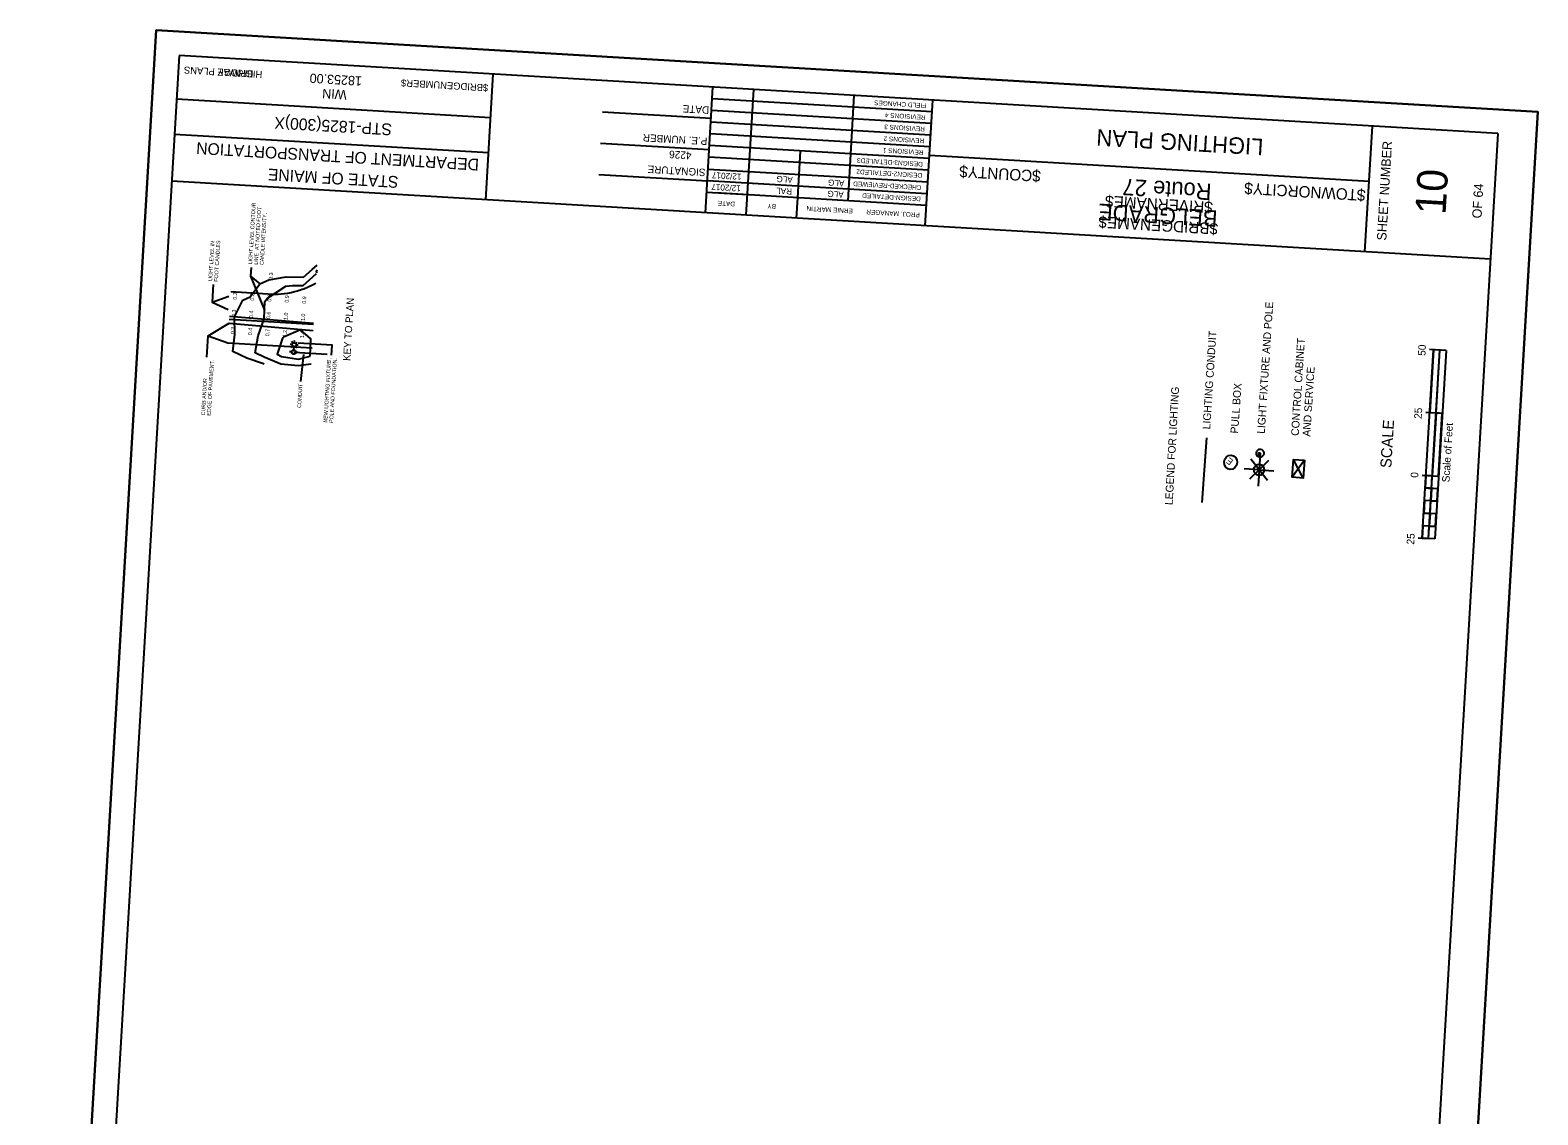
# Model space of a CAD drawing. Extents: x 1111000 to 1111599, y 618328 to 619209.
# Drawn here: x 1111000 to 1111599, y 618778 to 619209 of the extents above; entities that cross this region are included whole.
import ezdxf

# ---------------------------------------------------------------- set-up
doc = ezdxf.new("R2010")
doc.units = 0
for name, color, linetype in [('ANNOTATION', 7, 'Continuous'), ('BORDER', 7, 'Continuous'), ('BRIDGE_TITLE', 7, 'Continuous'), ('D_Lighting', 7, 'Continuous'), ('D_Utilities_Pole_StreetLight', 7, 'Continuous'), ('Default', 7, 'Continuous'), ('H_V CONTROLS', 7, 'Continuous'), ('HIGHWAY_TITLE', 7, 'Continuous'), ('Liting Text', 7, 'Continuous'), ('PLOT BOUNDARY', 7, 'Continuous'), ('Prp Liting', 7, 'Continuous'), ('UTILS GRND', 7, 'Continuous'), ('VSL-LUMINAIRES', 7, 'Continuous')]:
    doc.layers.add(name, color=color, linetype=linetype)

msp = doc.modelspace()

# ---------------------------------------------------------------- linework, layer by layer
at = {"layer": 'ANNOTATION'}
for p, q in [((1111087.16, 619111.54), (1111092.67, 619098.15)), ((1111094.11, 619104.46), (1111079.37, 619105.33)), ((1111071.9, 619101.33), (1111078.55, 619103.6)), ((1111078.62, 619092.89), (1111112.04, 619090.04)), ((1111112.18, 619092.36), (1111078.71, 619094.33)), ((1111112.2, 619092.79), (1111078.78, 619095.64)), ((1111070.35, 619087.89), (1111078.16, 619085.17)), ((1111078.16, 619085.17), (1111111.63, 619083.19)), ((1111102.8, 619081.83), (1111102.8, 619081.88)), ((1111102.96, 619084.58), (1111102.97, 619084.63)), ((1111103.95, 619080.99), (1111103.95, 619080.99)), ((1111103.97, 619081.33), (1111103.97, 619081.33)), ((1111104.3, 619080.97), (1111104.3, 619080.97)), ((1111104.32, 619081.31), (1111104.32, 619081.31)), ((1111105.71, 619084.42), (1111105.71, 619084.46)), ((1111107.09, 619069.78), (1111108.35, 619080.44))]:
    msp.add_line(p, q, dxfattribs=at)
for points in [[(1111092.58, 619076.67), (1111092.38, 619076.72), (1111085.63, 619079.09), (1111080.1, 619081.65), (1111080.93, 619088.5), (1111080.75, 619095.41), (1111084.05, 619102.11), (1111087.08, 619103.34), (1111090.89, 619108.6), (1111094.39, 619110.2), (1111101.35, 619111.33), (1111108.24, 619111.18), (1111111.7, 619114.27), (1111113.59, 619115.96)], [(1111087.37, 619115.05), (1111087.16, 619111.54), (1111090.89, 619108.6)], [(1111111.23, 619076.59), (1111106.12, 619075.95), (1111099.27, 619076.69), (1111092.54, 619079.4), (1111089.05, 619081.12), (1111090.18, 619087.95), (1111092.54, 619094.71), (1111092.81, 619101.59), (1111093.95, 619102.93), (1111101.13, 619107.58), (1111103.85, 619107.84), (1111108.04, 619107.89), (1111113.4, 619112.68)], [(1111072.32, 619108.34), (1111071.9, 619101.33), (1111078.28, 619098.39)], [(1111069.84, 619079.39), (1111070.35, 619087.89), (1111078.62, 619092.89)], [(1111110.84, 619079.84), (1111111.15, 619086.72), (1111106.99, 619090.32), (1111100.25, 619087.36), (1111099.89, 619086.99), (1111097.74, 619080.61), (1111099.46, 619079.75), (1111106.29, 619078.67), (1111110.84, 619079.84)], [(1111119.4, 619080.17), (1111119.64, 619084.23), (1111106.15, 619085.03)]]:
    msp.add_lwpolyline(points, dxfattribs=at)
for centre, major_axis, start_param, end_param in [((1111114.68, 619113.39), (0.86, 1.08), 1.737973, 2.633498), ((1111096.17, 619138.82), (21.5, 26.9), 3.756531, 4.064294), ((1111096.17, 619138.82), (21.5, 26.9), 4.064294, 4.213502), ((1111096.17, 619138.82), (21.5, 26.9), 4.213502, 4.323837), ((1111096.17, 619138.82), (21.5, 26.9), 4.323837, 4.333024)]:
    msp.add_ellipse(centre, major_axis=major_axis, ratio=0.998974, start_param=start_param, end_param=end_param, dxfattribs=at)
at = {"layer": 'BORDER'}
for p, q in [((1111058.79, 619199.23), (1111011.66, 618400.62)), ((1111582.86, 619168.3), (1111058.78, 619199.23)), ((1111180.66, 619141.96), (1111183.6, 619191.86)), ((1111182.57, 619174.51), (1111057.78, 619181.88)), ((1111267.96, 619136.8), (1111270.91, 619186.71)), ((1111270.17, 619174.23), (1111227.01, 619176.78)), ((1111355.31, 619131.64), (1111358.26, 619181.56)), ((1111530.01, 619121.33), (1111532.95, 619171.25)), ((1111181.74, 619160.56), (1111056.96, 619167.93)), ((1111269.43, 619161.76), (1111226.27, 619164.3)), ((1111535.75, 618369.69), (1111582.88, 619168.3)), ((1111531.65, 619149.24), (1111356.96, 619159.55)), ((1111579.92, 619118.39), (1111055.83, 619149.32)), ((1111268.7, 619149.28), (1111225.54, 619151.82))]:
    msp.add_line(p, q, dxfattribs=at)
for points in [[(1111357.97, 619176.91), (1111270.63, 619182.07)], [(1111284.18, 619135.84), (1111287.13, 619185.75)], [(1111324.59, 619141.55), (1111327.06, 619183.4)], [(1111357.69, 619172.26), (1111270.36, 619177.42)], [(1111357.42, 619167.61), (1111270.08, 619172.77)], [(1111357.14, 619162.96), (1111269.81, 619168.11)], [(1111356.59, 619153.66), (1111269.26, 619158.81)], [(1111356.87, 619158.31), (1111269.54, 619163.46)], [(1111304.62, 619142.72), (1111305.72, 619161.32)], [(1111268.99, 619154.16), (1111356.32, 619149.01)], [(1111356.05, 619144.36), (1111268.71, 619149.51)], [(1111284.66, 619143.9), (1111268.44, 619144.86)], [(1111355.77, 619139.71), (1111271.96, 619144.66)], [(1111304.15, 619134.66), (1111304.63, 619142.73)]]:
    msp.add_lwpolyline(points, dxfattribs=at)
at = {"layer": 'D_Lighting'}
for p, q in [((1111487.93, 619034.72), (1111484.62, 619038.92)), ((1111488.35, 619041.3), (1111487.93, 619034.72)), ((1111487.93, 619034.72), (1111491.76, 619038.46)), ((1111506.04, 619038.46), (1111501.03, 619031.77)), ((1111505.48, 619031.42), (1111501.59, 619038.81)), ((1111487.93, 619034.72), (1111482.01, 619035.1)), ((1111487.93, 619034.72), (1111484.1, 619030.98)), ((1111487.93, 619034.72), (1111487.51, 619028.14)), ((1111487.93, 619034.72), (1111493.85, 619034.34)), ((1111487.93, 619034.72), (1111491.24, 619030.52))]:
    msp.add_line(p, q, dxfattribs=at)
msp.add_lwpolyline([(1111506.04, 619038.46), (1111505.48, 619031.42), (1111501.03, 619031.77), (1111501.59, 619038.81)], close=True, dxfattribs=at)
for centre, major_axis in [((1111488.36, 619041.3), (0.11, 1.64)), ((1111487.93, 619034.72), (0.15, 2.24))]:
    msp.add_ellipse(centre, major_axis=major_axis, ratio=0.899857, dxfattribs=at)
at = {"layer": 'D_Utilities_Pole_StreetLight'}
for p, q in [((1111104.59, 619085.19), (1111104.64, 619085.99)), ((1111103.53, 619081.51), (1111102.71, 619081.57)), ((1111103.74, 619084.44), (1111102.94, 619084.49)), ((1111103.94, 619083.86), (1111103.33, 619083.33)), ((1111104.01, 619084.99), (1111103.48, 619085.59)), ((1111104.4, 619082.28), (1111104.49, 619083.59)), ((1111105.07, 619083.79), (1111105.59, 619083.19)), ((1111105.14, 619084.92), (1111105.74, 619085.45)), ((1111105.17, 619081.41), (1111105.99, 619081.36)), ((1111105.34, 619084.34), (1111106.13, 619084.29))]:
    msp.add_line(p, q, dxfattribs=at)
for centre, major_axis in [((1111104.35, 619081.46), (0.512, 0.641)), ((1111104.54, 619084.39), (-0.5, -0.626))]:
    msp.add_ellipse(centre, major_axis=major_axis, ratio=0.998974, dxfattribs=at)
at = {"layer": 'Default'}
msp.add_lwpolyline([(1110999.59, 618360.8), (1111049.67, 619209.32), (1111598.71, 619176.92), (1111548.64, 618328.39)], close=True, dxfattribs=at)
at = {"layer": 'H_V CONTROLS'}
for p, q in [((1111552.76, 619007.51), (1111557.24, 619082.37)), ((1111555.26, 619007.36), (1111559.73, 619082.23)), ((1111562.23, 619082.08), (1111555.68, 619082.47)), ((1111562.23, 619082.08), (1111557.75, 619007.21)), ((1111560.74, 619057.12), (1111554.19, 619057.51)), ((1111552.69, 619032.56), (1111559.25, 619032.17)), ((1111558.95, 619027.18), (1111553.96, 619027.47)), ((1111558.65, 619022.19), (1111553.66, 619022.48)), ((1111558.35, 619017.19), (1111553.36, 619017.49)), ((1111558.05, 619012.2), (1111553.06, 619012.5)), ((1111557.75, 619007.21), (1111551.2, 619007.6))]:
    msp.add_line(p, q, dxfattribs=at)
for points in [[(1111558.24, 619057.27), (1111559.73, 619082.23), (1111557.24, 619082.37), (1111555.75, 619057.42), (1111558.24, 619057.27)], [(1111558.24, 619057.27), (1111556.75, 619032.32), (1111559.25, 619032.17), (1111560.74, 619057.12), (1111558.24, 619057.27)], [(1111556.45, 619027.33), (1111556.75, 619032.32), (1111554.25, 619032.47), (1111553.96, 619027.47), (1111556.45, 619027.33)], [(1111556.15, 619022.33), (1111558.65, 619022.19), (1111558.95, 619027.18), (1111556.45, 619027.33), (1111556.15, 619022.33)], [(1111556.15, 619022.33), (1111553.66, 619022.48), (1111553.36, 619017.49), (1111555.86, 619017.34), (1111556.15, 619022.33)], [(1111555.56, 619012.35), (1111558.05, 619012.2), (1111558.35, 619017.19), (1111555.86, 619017.34), (1111555.56, 619012.35)], [(1111555.56, 619012.35), (1111553.06, 619012.5), (1111552.76, 619007.51), (1111555.26, 619007.36), (1111555.56, 619012.35)]]:
    msp.add_lwpolyline(points, dxfattribs=at)
at = {"layer": 'Liting Text'}
msp.add_line((1111104.35, 619081.46), (1111117.59, 619080.68), dxfattribs=at)
at = {"layer": 'PLOT BOUNDARY'}
msp.add_lwpolyline([(1111548.64, 618328.39), (1111598.71, 619176.92), (1111049.67, 619209.32), (1110999.59, 618360.8)], close=True, dxfattribs=at)
at = {"layer": 'Prp Liting'}
msp.add_line((1111465.3, 619021.72), (1111467.12, 619047.45), dxfattribs=at)
at = {"layer": 'UTILS GRND'}
msp.add_ellipse((1111476.65, 619037.69), major_axis=(-0.18, -2.87), ratio=0.901044, dxfattribs=at)
at = {"layer": 'VSL-LUMINAIRES'}
msp.add_lwpolyline([(1111488.46, 619041.29), (1111487.74, 619041.31), (1111487.73, 619040.55), (1111488.45, 619040.53)], close=True, dxfattribs=at)
msp.add_lwpolyline([(1111488.46, 619041.29), (1111487.74, 619041.31), (1111487.73, 619040.55), (1111488.45, 619040.53)], close=True, dxfattribs=at)
msp.add_lwpolyline([(1111488.35, 619041.3), (1111488.35, 619041.3)], dxfattribs=at)

# ---------------------------------------------------------------- texts
at = {"layer": 'ANNOTATION'}
for s, height, rotation, p in [('4226', 3, 176.62273, (1111262.5, 619160.97)), ('LIGHT LEVEL CONTOUR', 1.528, 86.56399, (1111087.77, 619116.25)), ('LINE  AT NOTED FOOT', 1.528, 86.56399, (1111090.06, 619116.12)), ('CANDLE INTENSITY.', 1.528, 86.56399, (1111092.34, 619115.98)), ('LIGHT LEVEL IN', 1.528, 86.56399, (1111071.88, 619109.48)), ('FOOT CANDLES', 1.528, 86.56399, (1111074.17, 619109.35)), ('0.3', 1.528, 86.56399, (1111095.91, 619110.11)), ('0.3', 1.528, 86.56399, (1111081.65, 619102.25)), ('0.3', 1.528, 86.56399, (1111088.52, 619101.85)), ('0.6', 1.528, 86.56399, (1111095.39, 619101.44)), ('0.3', 1.528, 86.56399, (1111081.24, 619095.38)), ('0.9', 1.528, 86.56399, (1111102.26, 619101.03)), ('0.9', 1.528, 86.56399, (1111109.14, 619100.63)), ('KEY TO PLAN', 2.8603, 86.56399, (1111126.77, 619077.88)), ('0.4', 1.528, 86.56399, (1111088.11, 619094.97)), ('0.6', 1.528, 86.56399, (1111094.98, 619094.57)), ('1.0', 1.528, 86.56399, (1111101.85, 619094.16)), ('1.0', 1.528, 86.56399, (1111108.72, 619093.76)), ('0.3', 1.528, 86.56399, (1111080.83, 619088.51)), ('0.4', 1.528, 86.56399, (1111087.7, 619088.1)), ('0.7', 1.528, 86.56399, (1111094.57, 619087.7)), ('1.2', 1.528, 86.56399, (1111101.44, 619087.29)), ('1.4', 1.528, 86.56399, (1111108.31, 619086.88)), ('EDGE OF PAVEMENT.', 1.528, 86.56399, (1111071.34, 619056.14)), ('NEW LIGHTING FIXTURE,', 1.528, 86.56399, (1111117.65, 619053.4)), ('POLE AND FOUNDATION.', 1.528, 86.56399, (1111119.94, 619053.27)), ('CURB AND/OR', 1.528, 86.56399, (1111069.05, 619056.27)), ('CONDUIT', 1.528, 86.56399, (1111107.25, 619059.26))]:
    msp.add_text(s, height=height, rotation=rotation, dxfattribs=at).set_placement(p)
at = {"layer": 'BORDER'}
for s, height, rotation, p in [('18253.00', 3.726, 176.62273, (1111131.53, 619190.91)), ('WIN', 3.726, 176.62273, (1111125.45, 619185.46)), ('STP-1825(300)X', 4.6588, 176.62273, (1111143.48, 619172.15)), ('DATE', 2.953, 176.62273, (1111269.49, 619178.99)), ('FIELD CHANGES', 1.8637, 176.62273, (1111355.73, 619180.22)), ('REVISIONS 4', 1.8637, 176.62273, (1111355.46, 619175.57)), ('REVISIONS 3', 1.8637, 176.62273, (1111355.18, 619170.92)), ('LIGHTING PLAN', 6.5214, 176.62273, (1111489.8, 619166.1)), ('DEPARTMENT OF TRANSPORTATION', 4.6588, 176.62273, (1111178.05, 619158.17)), ('P.E. NUMBER', 2.9528, 176.62273, (1111268.76, 619166.61)), ('REVISIONS 2', 1.8637, 176.62273, (1111354.91, 619166.27)), ('SHEET NUMBER', 3.7264, 86.62273, (1111538.46, 619125.67)), ('DESIGN3-DETAILED3', 1.8637, 176.62273, (1111354.36, 619156.97)), ('REVISIONS 1', 1.8637, 176.62273, (1111354.63, 619161.62)), ('STATE OF MAINE', 4.6588, 176.62273, (1111146.06, 619151.28)), ('SIGNATURE', 2.953, 176.62273, (1111268.03, 619154.23)), ('12/2017', 2.423, 176.62273, (1111282.31, 619152.25)), ('DESIGN2-DETAILED2', 1.8637, 176.62273, (1111354.1, 619152.5)), ('10', 12.097, 86.62273, (1111562.02, 619135.83)), ('12/2017', 2.423, 176.62273, (1111282.04, 619147.6)), ('RAL', 2.423, 176.62273, (1111302.41, 619146.4)), ('ALG', 2.423, 176.62273, (1111302.69, 619151.05)), ('ALG', 2.423, 176.62273, (1111323.2, 619149.65)), ('CHECKED-REVIEWED', 1.8637, 176.62273, (1111353.81, 619147.67)), ('OF 64', 3.726, 86.62273, (1111576.31, 619134.46)), ('DATE', 1.857, 176.62273, (1111279.71, 619141.14)), ('BY', 1.857, 176.62273, (1111296.03, 619140.17)), ('ALG', 2.423, 176.62273, (1111322.94, 619145.19)), ('DESIGN-DETAILED', 1.8637, 176.62273, (1111353.55, 619143.2)), ('ERNIE MARTIN', 1.8637, 176.62273, (1111326.55, 619138.37)), ('PROJ. MANAGER', 1.8637, 176.62273, (1111353.17, 619136.8))]:
    msp.add_text(s, height=height, rotation=rotation, dxfattribs=at).set_placement(p)
at = {"layer": 'BRIDGE_TITLE'}
for s, height, p in [('BRIDGE PLANS', 2.795, (1111088.37, 619193.27)), ('$BRIDGENUMBER$', 2.795, (1111181.68, 619187.76)), ('$COUNTY$', 4.536, (1111401.29, 619153.57)), ('$TOWNORCITY$', 4.5358, (1111530.35, 619145.96)), ('$RIVERNAME$', 4.5358, (1111469.65, 619141.14)), ('$BRIDGENAME$', 4.5358, (1111471.73, 619132.62))]:
    msp.add_text(s, height=height, rotation=176.62273, dxfattribs=at).set_placement(p)
at = {"layer": 'H_V CONTROLS'}
for s, height, p in [('50', 3, (1111554.02, 619079.89)), ('25', 3, (1111552.52, 619054.84)), ('SCALE', 4.375, (1111540.46, 619035.31)), ('Scale of Feet', 3, (1111563.6, 619029.65)), ('0', 3, (1111551.13, 619031.45)), ('25', 3, (1111549.54, 619004.93))]:
    msp.add_text(s, height=height, rotation=86.58074, dxfattribs=at).set_placement(p)
at = {"layer": 'HIGHWAY_TITLE'}
for s, height, p in [('HIGHWAY PLANS', 2.795, (1111091.91, 619193.06)), ('Route 27', 6.521, (1111469.2, 619148.26)), ('BELGRADE', 6.521, (1111471.59, 619137.67))]:
    msp.add_text(s, height=height, rotation=176.62273, dxfattribs=at).set_placement(p)
at = {"layer": 'Liting Text'}
for s, height, rotation, p in [('LIGHT FIXTURE AND POLE', 3.0627, 86.29777, (1111490.18, 619048.93)), ('LIGHTING CONDUIT', 3.0627, 86.29777, (1111468.5, 619050.7)), ('CONTROL CABINET ', 3.0627, 86.37642, (1111503.69, 619048.11)), ('AND SERVICE', 3.0627, 86.37642, (1111508.28, 619047.81)), ('PULL BOX', 3.063, 85.94528, (1111479.58, 619049.02)), ('LEGEND FOR LIGHTING', 3.0627, 86.82995, (1111453.56, 619020.62))]:
    msp.add_text(s, height=height, rotation=rotation, dxfattribs=at).set_placement(p)
at = {"layer": 'UTILS GRND'}
msp.add_text('E', height=2.58, rotation=143.58614, dxfattribs=at).set_placement((1111477.9, 619038.39))

doc.saveas('drawing.dxf')
